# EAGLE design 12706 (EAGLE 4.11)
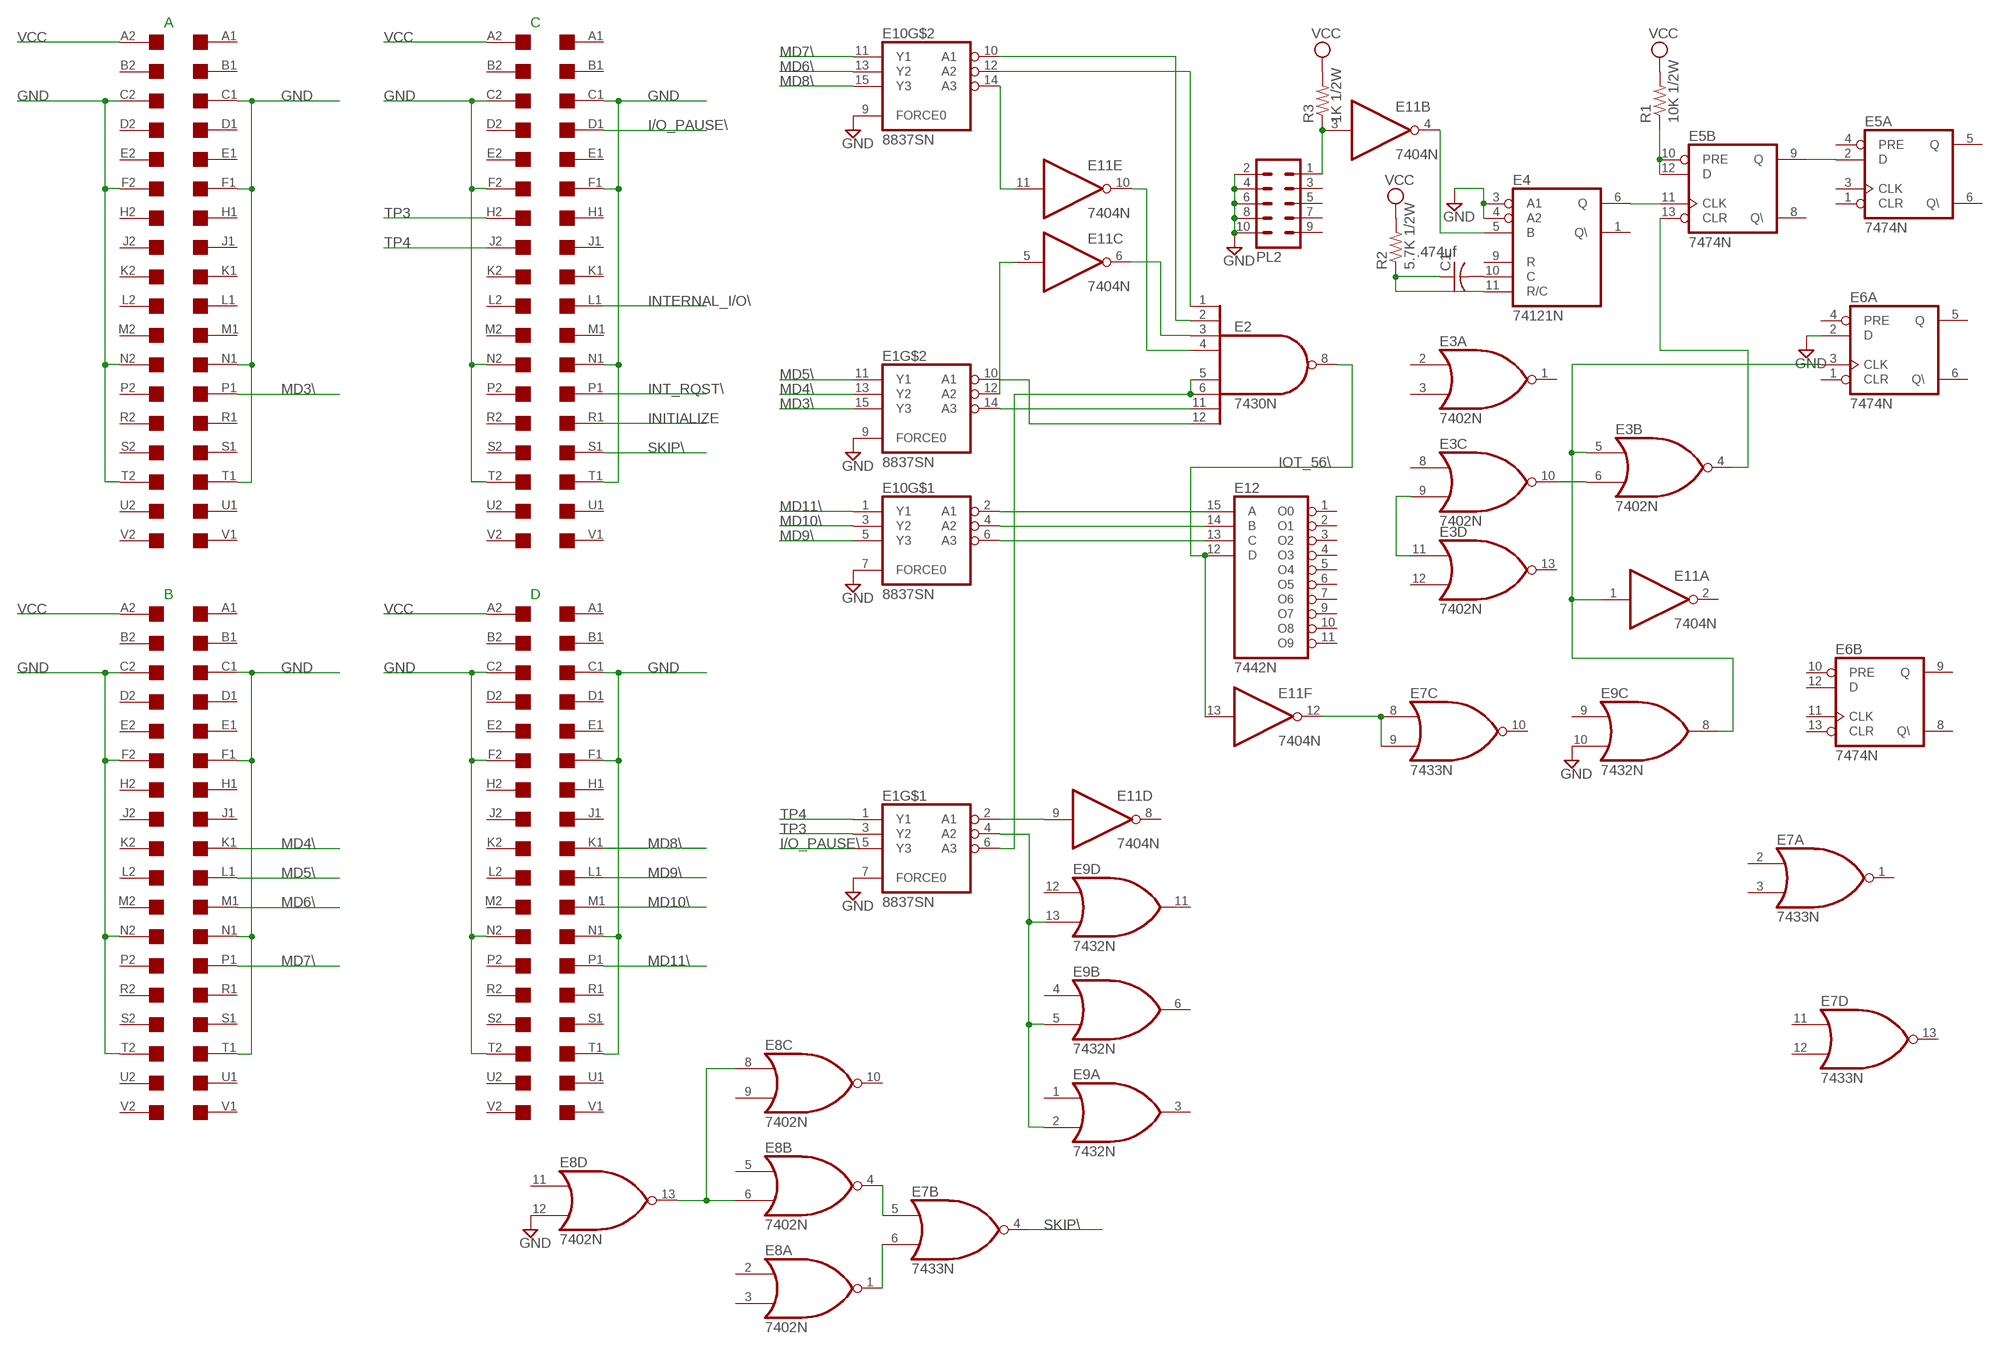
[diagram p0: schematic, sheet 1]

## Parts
A  DEC-FLIPCHIP  [DEC-FLIPCHIP]
B  DEC-FLIPCHIP  [DEC-FLIPCHIP]
C  DEC-FLIPCHIP  [DEC-FLIPCHIP]
C1  .474uf  C-US050-045X075  [C050-045X075]
D  DEC-FLIPCHIP  [DEC-FLIPCHIP]
E1  8837SN  [DIL16]
E2  7430N  [DIL14]
E3  7402N  [DIL14]
E4  74121N  [DIL14]
E5  7474N  74S74N  [DIL14]
E6  7474N  74S74N  [DIL14]
E7  7433N  74LS33N  [DIL14]
E8  7402N  [DIL14]
E9  7432N  [DIL14]
E10  8837SN  [DIL16]
E11  7404N  [DIL14]
E12  7442N  74LS42N  [DIL16]
PL2  10H  [10H]
R1  10K 1/2W  R-US_0204/7  [0204/7]
R2  5.7K 1/2W  R-US_0204/7  [0204/7]
R3  1K 1/2W  R-US_0204/7  [0204/7]

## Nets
GND [Power]: A.C1 A.C2 A.F1 A.F2 A.N1 A.N2 A.T1 A.T2 B.C1 B.C2 B.F1 B.F2 B.N1 B.N2 B.T1 B.T2 C.C1 C.C2 C.F1 C.F2 C.N1 C.N2 C.T1 C.T2 D.C1 D.C2 D.F1 D.F2 D.N1 D.N2 D.T1 D.T2 E1.7(FORCE0) E1.9(FORCE0) E4.3(A1) E4.4(A2) E6.2(A:D) E8.12(D:I1) E9.10(C:I1) E10.7(FORCE0) E10.9(FORCE0) PL2.2 PL2.4 PL2.6 PL2.8 PL2.10
I/O_PAUSE\: C.D1 E1.5(Y3)
INITIALIZE: C.R1
INT_RQST\: C.P1
INTERNAL_I/O\: C.L1
IOT_56\: E2.8(O) E11.13(F:I) E12.12(D)
MD3\: A.P1 E1.15(Y3)
MD4\: B.K1 E1.13(Y2)
MD5\: B.L1 E1.11(Y1)
MD6\: B.M1 E10.13(Y2)
MD7\: B.P1 E10.11(Y1)
MD8\: D.K1 E10.15(Y3)
MD9\: D.L1 E10.5(Y3)
MD10\: D.M1 E10.3(Y2)
MD11\: D.P1 E10.1(Y1)
N$1: E1.14(A3) E2.11(I6)
N$2: E1.10(A1) E2.12(I7)
N$3: E10.2(A1) E12.15(A)
N$4: E10.4(A2) E12.14(B)
N$5: E10.6(A3) E12.13(C)
N$6 [Power]: E7.6(B:I1) E8.1(A:O)
N$7: E7.8(C:I0) E7.9(C:I1) E11.12(F:O)
N$8: E1.2(A1) E11.9(D:I)
N$9 [Power]: E1.4(A2) E9.2(A:I1) E9.5(B:I1) E9.13(D:I1)
N$10: E1.6(A3) E2.5(I4) E2.6(I5)
N$11: E2.4(I3) E11.10(E:O)
N$12: E2.1(I0) E10.12(A2)
N$13: E2.2(I1) E10.10(A1)
N$14: E2.3(I2) E11.6(C:O)
N$15: E1.12(A2) E11.5(C:I)
N$16: E10.14(A3) E11.11(E:I)
N$17: E7.5(B:I0) E8.4(B:O)
N$18: E8.6(B:I1) E8.8(C:I0) E8.13(D:O)
N$19: C1.1 E4.11(R/C) R2.1
N$20: E5.2(A:D) E5.9(B:Q)
N$21: E5.10(B:PRE) E5.12(B:D) R1.1
N$22: E3.6(B:I1) E3.10(C:O)
N$23: E3.9(C:I1) E3.11(D:I0)
N$24: C1.2 E4.10(C)
N$25: E4.6(Q) E5.11(B:CLK)
N$26: E4.5(B) E11.4(B:O)
N$27: E11.3(B:I) PL2.1 R3.1
N$29: E3.4(B:O) E5.13(B:CLR)
N$30: E3.5(B:I0) E6.3(A:CLK) E9.8(C:O) E11.1(A:I)
SKIP\ [Power]: C.S1 E7.4(B:O)
TP3: C.H2 E1.3(Y2)
TP4: C.J2 E1.1(Y1)
VCC [Power]: A.A2 B.A2 C.A2 D.A2 R1.2 R2.2 R3.2
Unconnected: A.A1 A.B1 A.B2 A.D1 A.D2 A.E1 A.E2 A.H1 A.H2 A.J1 A.J2 A.K1 A.K2 A.L1 A.L2 A.M1 A.M2 A.P2 A.R1 A.R2 A.S1 A.S2 A.U1 A.U2 A.V1 A.V2 B.A1 B.B1 B.B2 B.D1 B.D2 B.E1 B.E2 B.H1 B.H2 B.J1 B.J2 B.K2 B.L2 B.M2 B.P2 B.R1 B.R2 B.S1 B.S2 B.U1 B.U2 B.V1 B.V2 C.A1 C.B1 C.B2 C.D2 C.E1 C.E2 C.H1 C.J1 C.K1 C.K2 C.L2 C.M1 C.M2 C.P2 C.R2 C.S2 C.U1 C.U2 C.V1 C.V2 D.A1 D.B1 D.B2 D.D1 D.D2 D.E1 D.E2 D.H1 D.H2 D.J1 D.J2 D.K2 D.L2 D.M2 D.P2 D.R1 D.R2 D.S1 D.S2 D.U1 D.U2 D.V1 D.V2 E3.1(A:O) E3.2(A:I0) E3.3(A:I1) E3.8(C:I0) E3.12(D:I1) E3.13(D:O) E4.1(Q\) E4.9(R) E5.1(A:CLR) E5.3(A:CLK) E5.4(A:PRE) E5.5(A:Q) E5.6(A:Q\) E5.8(B:Q\) E6.1(A:CLR) E6.4(A:PRE) E6.5(A:Q) E6.6(A:Q\) E6.8(B:Q\) E6.9(B:Q) E6.10(B:PRE) E6.11(B:CLK) E6.12(B:D) E6.13(B:CLR) E7.1(A:O) E7.2(A:I0) E7.3(A:I1) E7.10(C:O) E7.11(D:I0) E7.12(D:I1) E7.13(D:O) E8.2(A:I0) E8.3(A:I1) E8.5(B:I0) E8.9(C:I1) E8.10(C:O) E8.11(D:I0) E9.1(A:I0) E9.3(A:O) E9.4(B:I0) E9.6(B:O) E9.9(C:I0) E9.11(D:O) E9.12(D:I0) E11.2(A:O) E11.8(D:O) E12.1(O0) E12.2(O1) E12.3(O2) E12.4(O3) E12.5(O4) E12.6(O5) E12.7(O6) E12.9(O7) E12.10(O8) E12.11(O9) PL2.3 PL2.5 PL2.7 PL2.9

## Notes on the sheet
- A | C
- B | D

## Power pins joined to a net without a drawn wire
GND: E1.8(P:GND) E2.7(GND) E3.7(P:GND) E4.7(GND) E5.7(P:GND) E6.7(P:GND) E7.7(P:GND) E8.7(P:GND) E9.7(P:GND) E10.8(P:GND) E11.7(P:GND) E12.8(GND)
VCC: E1.16(P:VCC) E2.14(VCC) E3.14(P:VCC) E4.14(VCC) E5.14(P:VCC) E6.14(P:VCC) E7.14(P:VCC) E8.14(P:VCC) E9.14(P:VCC) E10.16(P:VCC) E11.14(P:VCC) E12.16(VCC)

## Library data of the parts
A B C D = con-dec:DEC-FLIPCHIP: Two-sided DEC Flip-Chip single card fingers
C1 = rcl:C-US: CAPACITOR, American symbol
E1 E10 = dec-con:8837: Hex inverting LINE RECEIVER
E2 = 74xx-us:74*30: 8-input NAND gate
E3 E8 = 74xx-us:74*02: Quad 2-input NOR gate
E4 = 74xx-us:74*121: Monostable MULTIVIBRATOR, schmitt trigger inputs
E5 E6 = 74xx-us:74*74: Dual D type positive edge triggered FLIP FLOP, preset and clear
E7 = 74xx-us:74*33: Quad 2-input NOR buffer, open collector
E9 = 74xx-us:74*32: Quad 2-input OR gate
E11 = 74xx-us:74*04: Hex INVERTER
E12 = 74xx-us:74*42: 4-line to 10-line DECODER (1-of-10)
PL2 = con-harting-h:10H: CONNECTOR
R1-R3 = rcl:R-US_: RESISTOR, American symbol

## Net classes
1 Power: width 0.381 mm, drill 0.381 mm, clearance 0.381 mm

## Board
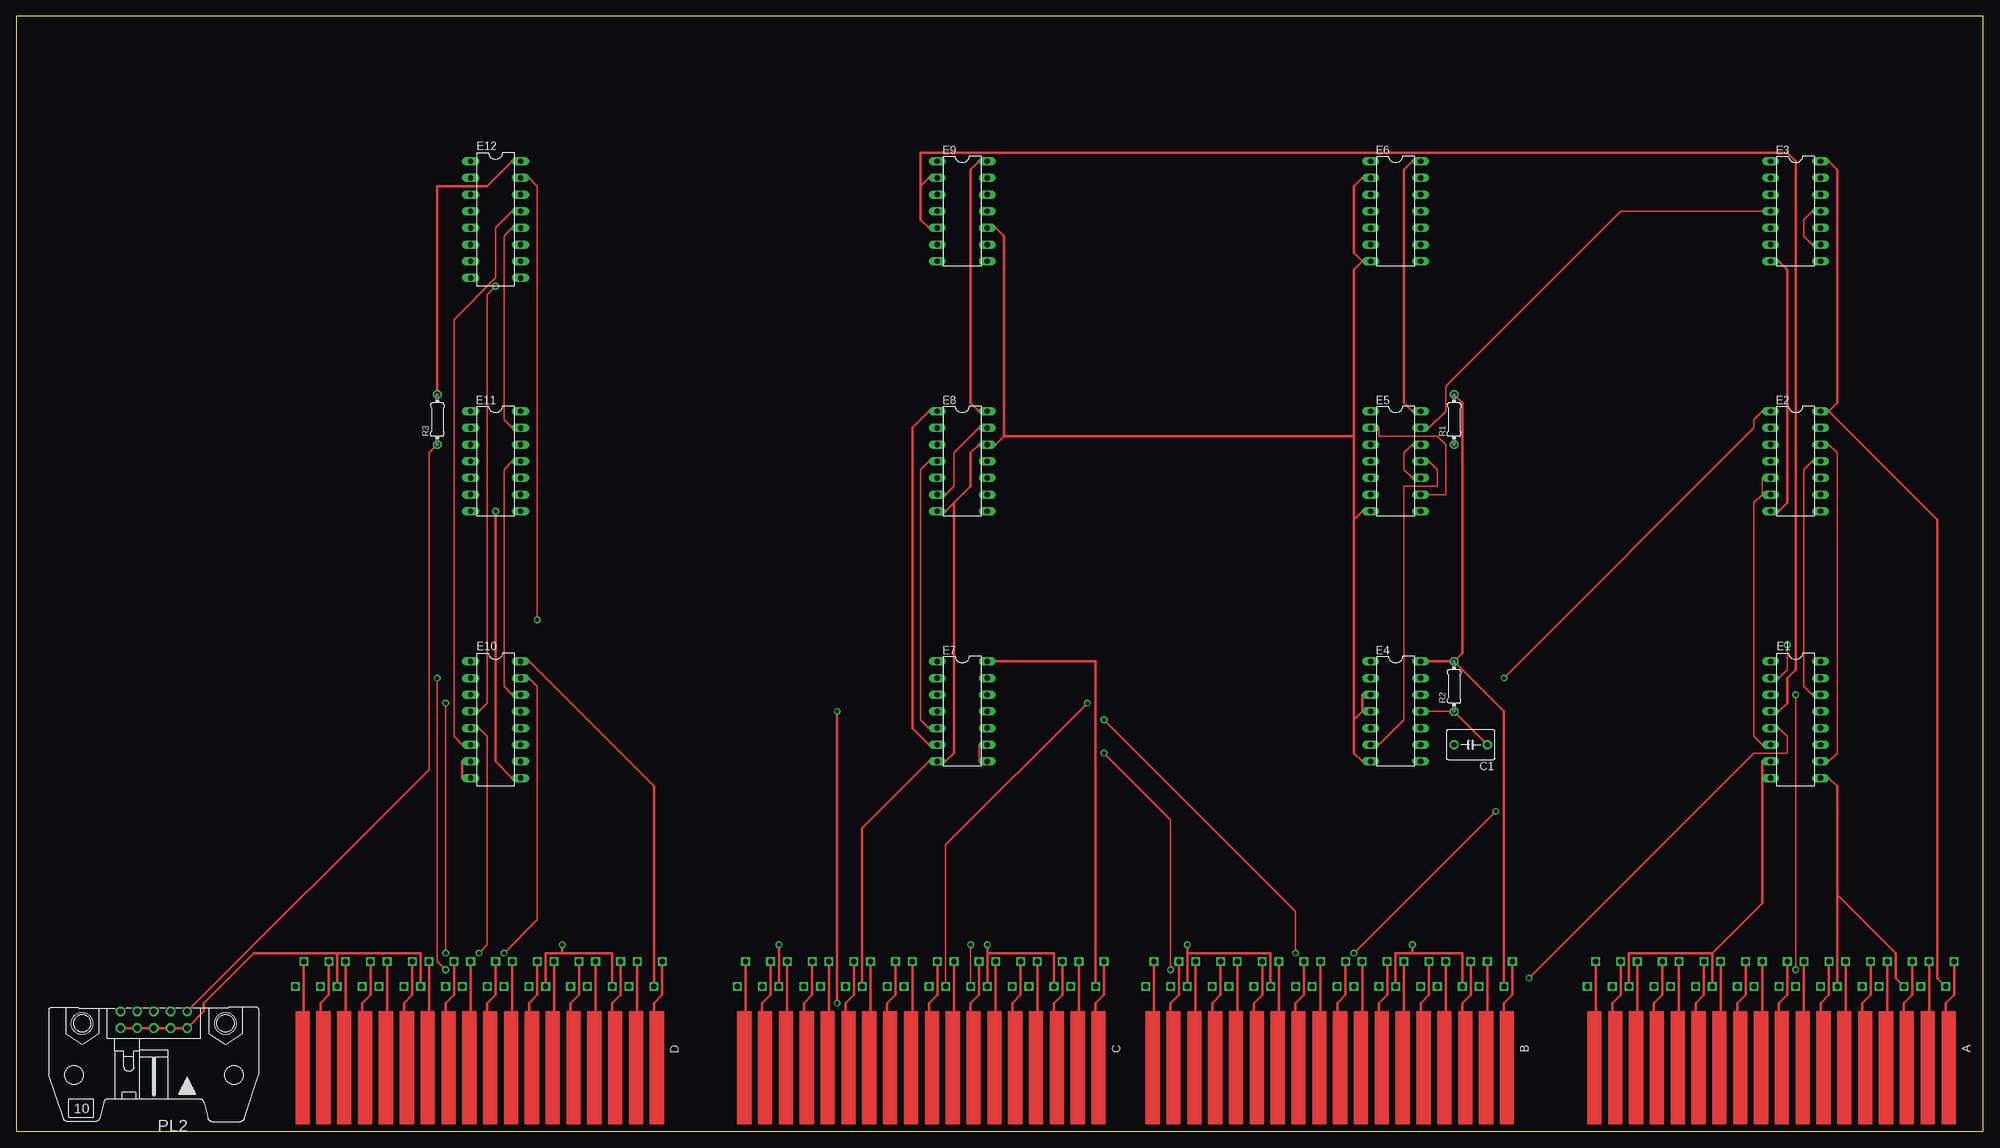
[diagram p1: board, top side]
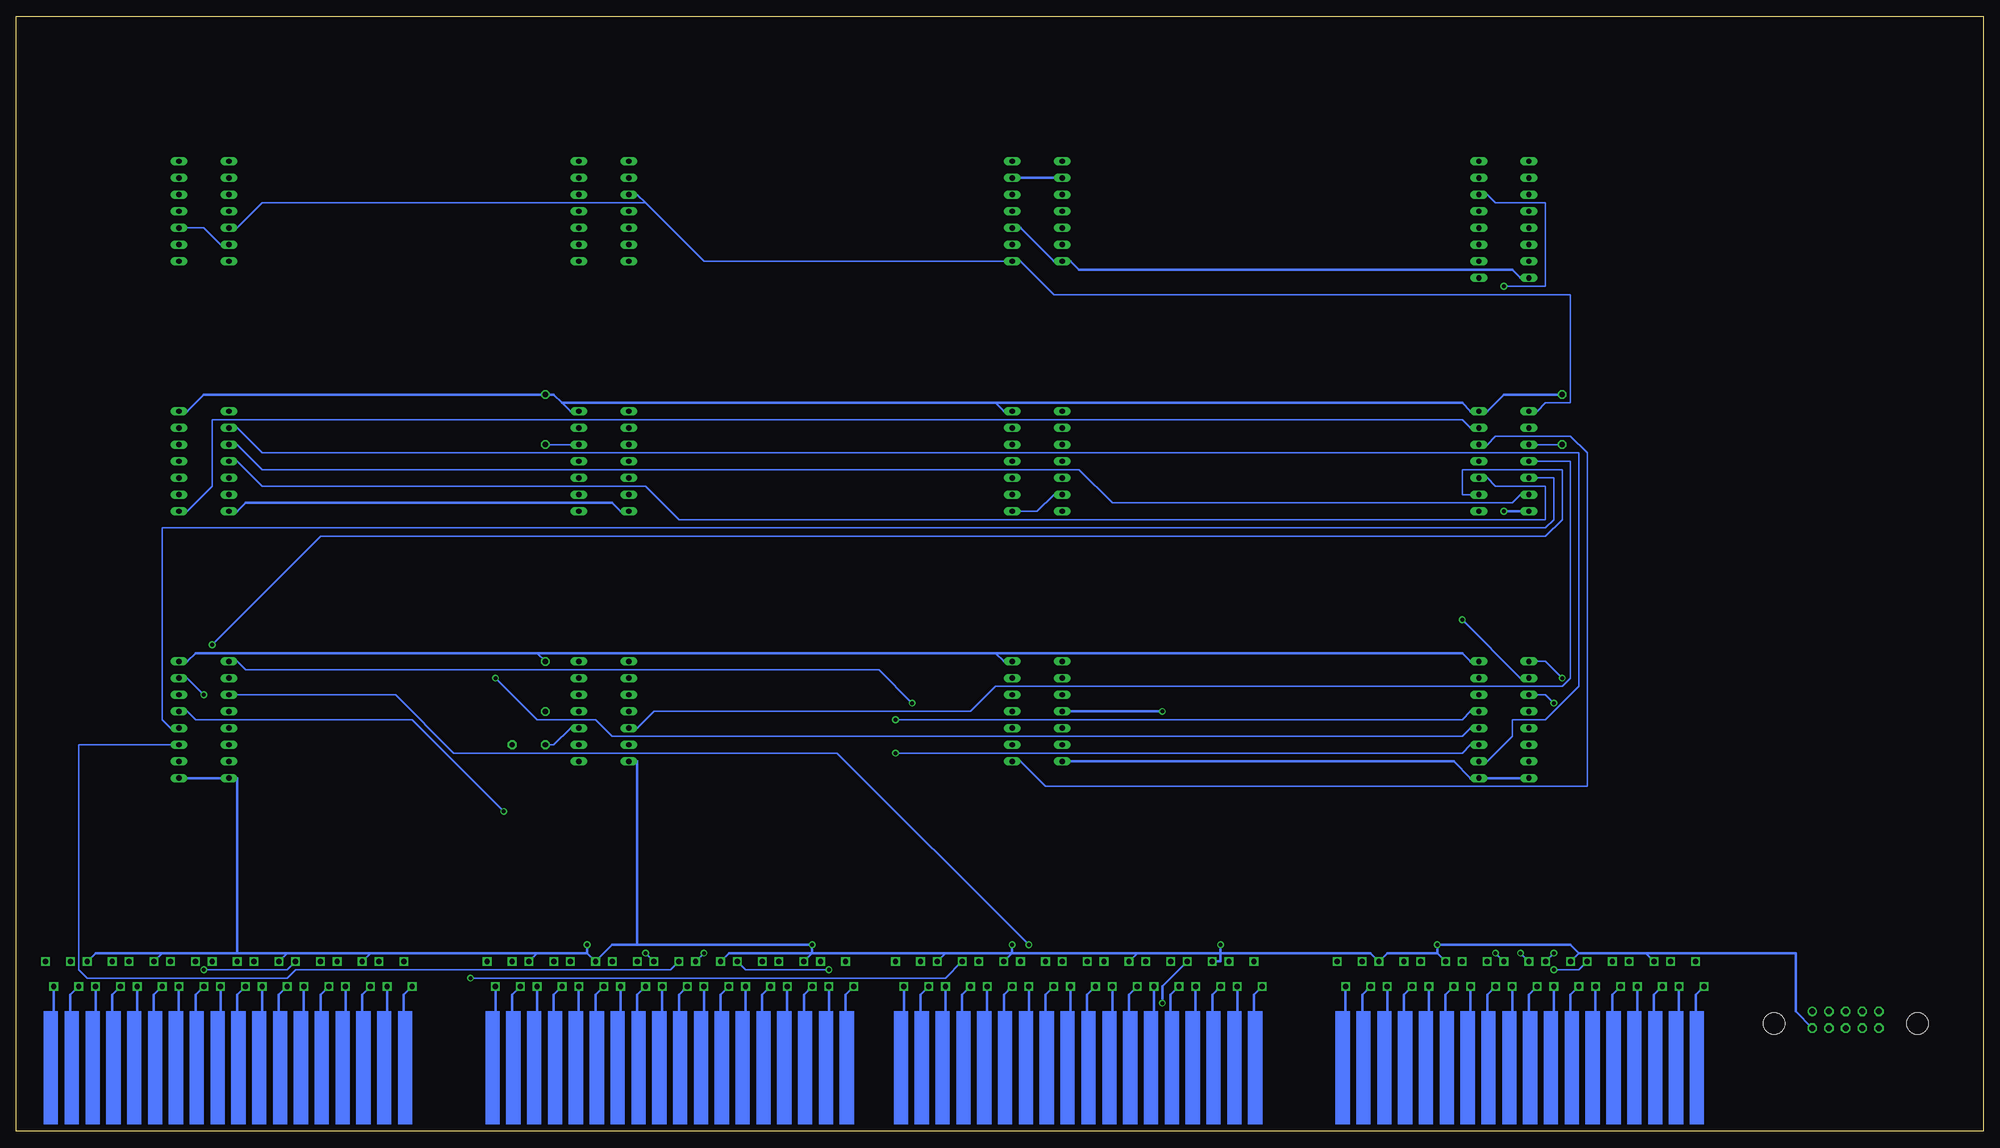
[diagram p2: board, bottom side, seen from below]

Size 299.7 x 169.85 mm. Coordinates in mm from the lower left corner, seen from the top.
Outline: 0,0 299.7,0 299.7,169.85 0,169.85 0,0
Copper layers (1*16): Top 0.035mm / dielectric 1.5mm / Bottom 0.035mm
Design rules "default": minimum track width 10mil, minimum drill 24mil, track to track 8mil, track to pad 8mil, pad to pad 8mil, via to via 8mil, smd to smd 8mil, copper to edge 40mil, drill to drill 8mil, minimum pad ring 10mil, minimum via ring 8mil, stop-mask expansion 4mil, vias tented up to drill 0mil, thermal gap 10mil

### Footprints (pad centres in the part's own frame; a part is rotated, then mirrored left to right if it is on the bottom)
DEC-FLIPCHIP = drill 0.813 square: A1 -7.62,27.94; A2 -3.81,26.67; B1 -7.62,24.13; B2 -3.81,22.86; C1 -7.62,21.59; C2 -3.81,20.32; D1 -7.62,17.78; D2 -3.81,16.51; E1 -7.62,15.24; E2 -3.81,13.97; F1 -7.62,11.43; F2 -3.81,10.16; H1 -7.62,8.89; H2 -3.81,7.62; J1 -7.62,5.08; J2 -3.81,3.81; K1 -7.62,2.54; K2 -3.81,1.27; L1 -7.62,-1.27; L2 -3.81,-2.54; M1 -7.62,-3.81; M2 -3.81,-5.08; N1 -7.62,-7.62; N2 -3.81,-8.89; P1 -7.62,-10.16; P2 -3.81,-11.43; R1 -7.62,-13.97; R2 -3.81,-15.24; S1 -7.62,-16.51; S2 -3.81,-17.78; T1 -7.62,-20.32; T2 -3.81,-21.59; U1 -7.62,-22.86; U2 -3.81,-24.13; V1 -7.62,-26.67; V2 -3.81,-27.94
C050-045X075 = drill 0.813 octagon: 1 -2.54,0; 2 2.54,0
DIL16 = drill 0.813 long: 1 -8.89,-3.81; 2 -6.35,-3.81; 3 -3.81,-3.81; 4 -1.27,-3.81; 5 1.27,-3.81; 6 3.81,-3.81; 7 6.35,-3.81; 8 8.89,-3.81; 9 8.89,3.81; 10 6.35,3.81; 11 3.81,3.81; 12 1.27,3.81; 13 -1.27,3.81; 14 -3.81,3.81; 15 -6.35,3.81; 16 -8.89,3.81
DIL14 = drill 0.813 long: 1 -7.62,-3.81; 2 -5.08,-3.81; 3 -2.54,-3.81; 4 0,-3.81; 5 2.54,-3.81; 6 5.08,-3.81; 7 7.62,-3.81; 8 7.62,3.81; 9 5.08,3.81; 10 2.54,3.81; 11 0,3.81; 12 -2.54,3.81; 13 -5.08,3.81; 14 -7.62,3.81
10H = drill 0.914 round: 1 -5.08,-1.27 | drill 0.914 octagon: 2 -5.08,1.27; 3 -2.54,-1.27; 4 -2.54,1.27; 5 0,-1.27; 6 0,1.27; 7 2.54,-1.27; 8 2.54,1.27; 9 5.08,-1.27; 10 5.08,1.27 | hole 3.302: -10.922,0.533; 10.922,0.533
0204/7 = drill 0.813 octagon: 1 -3.81,0; 2 3.81,0

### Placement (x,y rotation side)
A  267.33,18.25 270 top
B  200.02,18.25 270 top
C  137.79,18.25 270 top
C1  221.61,58.89 180 top
D  70.48,18.25 270 top
E1  271.14,62.7 270 top
E2  271.14,102.07 270 top
E3  271.14,140.17 270 top
E4  210.18,63.97 270 top
E5  210.18,102.07 270 top
E6  210.18,140.17 270 top
E7  144.14,63.97 270 top
E8  144.14,102.07 270 top
E9  144.14,140.17 270 top
E10  73.02,62.7 270 top
E11  73.02,102.07 270 top
E12  73.02,138.9 270 top
PL2  20.95,16.98 180 top
R1  219.07,108.42 90 top
R2  219.07,67.78 90 top
R3  64.13,108.42 90 top

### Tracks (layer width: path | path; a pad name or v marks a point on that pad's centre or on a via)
GND  (via drill 0.61)
  Top 0.381: E10.8 67.94,53.81 67.94,56.35 E10.7 | v73.02,94.45 73.02,56.35 75.56,53.81 E10.9 | C.N2 128.9,46.19 139.06,56.35 E7.7 141.6,56.35 142.87,57.62 142.87,95.72 | 142.87,95.72 145.41,98.26 145.41,103.34 146.68,104.61 E8.12 149.22,104.61 150.49,105.88 | 142.87,95.72 141.6,94.45 E8.7 | 150.49,105.88 150.49,136.36 149.22,137.63 E9.10 | E2.7 268.6,94.45 269.87,95.72 269.87,131.28 268.6,132.55 E3.7 | 205.1,132.55 203.83,133.82 203.83,143.98 205.1,145.25 E6.2 | 205.1,132.55 E6.7 205.1,132.55 | 203.83,62.7 203.83,57.62 205.1,56.35 E4.7 | 203.83,62.7 205.1,63.97 | 205.1,63.97 E4.4 205.1,63.97 | 205.1,63.97 205.1,66.51 E4.3 | 203.83,93.18 205.1,94.45 E5.7 | 203.83,93.18 203.83,62.7 | 205.1,132.55 203.83,131.28 203.83,105.88 | 203.83,105.88 203.83,93.18 | A.T2 245.74,27.14 258.44,27.14 | 258.44,27.14 A.N2 | 266.06,53.81 266.06,56.35 E1.7 | 266.06,53.81 E1.8 266.06,53.81 | 277.49,36.03 277.49,52.54 276.22,53.81 E1.9 | 277.49,36.03 A.F2 | A.C2 286.38,23.33 286.38,27.14 277.49,36.03 | 258.44,27.14 266.06,34.76 266.06,53.81 | B.F2 210.18,27.14 212.72,27.14 | 212.72,27.14 220.34,27.14 B.C2 | v212.72,28.41 212.72,27.14 | 48.89,27.14 D.T2 | 48.89,27.14 61.59,27.14 D.N2 | PL2.10 PL2.8 PL2.6 PL2.4 PL2.2 28.57,18.25 28.57,19.52 36.19,27.14 48.89,27.14 | 178.43,27.14 B.T2 | 178.43,27.14 191.13,27.14 B.N2 | 147.95,27.14 C.F2 | 147.95,27.14 158.11,27.14 C.C2 | D.F2 80.64,27.14 83.18,27.14 | 83.18,27.14 90.8,27.14 D.C2 | v116.2,28.41 C.T2 | v83.18,28.41 83.18,27.14 | v147.95,28.41 147.95,27.14 | v178.43,28.41 178.43,27.14 | 150.49,105.88 203.83,105.88
  Bottom 0.381: E10.8 70.48,53.81 75.56,53.81 E10.9 78.1,53.81 80.64,56.35 139.06,56.35 E7.7 | v73.02,94.45 70.48,94.45 E11.7 | E12.8 70.48,130.01 71.75,131.28 137.79,131.28 139.06,132.55 E9.7 141.6,132.55 146.68,137.63 E9.10 | E2.7 266.06,94.45 264.79,95.72 208.91,95.72 207.64,94.45 E5.7 | E1.9 273.68,53.81 268.6,53.81 E1.8 266.06,53.81 266.06,27.14 | 212.72,27.14 B.F1 208.91,28.41 205.1,28.41 | 212.72,27.14 220.34,27.14 | 220.34,27.14 B.C1 | 245.74,27.14 A.T1 | 220.34,27.14 245.74,27.14 | 258.44,27.14 A.N1 | 245.74,27.14 258.44,27.14 | 277.49,27.14 A.F1 | 258.44,27.14 266.06,27.14 | 266.06,27.14 277.49,27.14 | A.C1 287.65,27.14 277.49,27.14 | 212.72,27.14 v212.72,28.41 | 51.43,27.14 D.T1 | 61.59,27.14 51.43,27.14 | 61.59,27.14 D.N1 | PL2.2 28.57,18.25 28.57,27.14 51.43,27.14 | 83.18,27.14 D.F1 | 83.18,27.14 90.8,27.14 D.C1 93.34,27.14 116.2,27.14 | 116.2,27.14 116.2,25.87 C.T1 | 116.2,27.14 v116.2,28.41 | 128.9,27.14 C.N1 | 128.9,27.14 116.2,27.14 | 147.95,27.14 C.F1 | 147.95,27.14 128.9,27.14 | 158.11,27.14 C.C1 | 158.11,27.14 147.95,27.14 | 178.43,27.14 B.T1 | 178.43,27.14 158.11,27.14 | B.N1 191.13,27.14 178.43,27.14 | 83.18,27.14 v83.18,28.41 62.86,28.41 61.59,27.14 | 147.95,27.14 v147.95,28.41 | 178.43,27.14 v178.43,28.41 205.1,28.41 | 205.1,28.41 205.1,56.35 E4.7
I/O_PAUSE\  (via drill 0.61)
  Top 0.254: v230.5,23.33 264.79,57.62 269.87,57.62 269.87,60.16 268.6,61.43 E1.5
  Bottom 0.254: C.D1 158.11,23.33 v230.5,23.33
IOT_56\
  Top 0.254: E11.13 75.56,107.15 74.29,108.42 74.29,136.36 75.56,137.63 E12.12
  Bottom 0.254: E2.8 273.68,94.45 269.87,98.26 269.87,108.42 79.37,108.42 78.1,107.15 E11.13
MD3\  (via drill 0.61)
  Top 0.254: v271.14,24.6 v271.14,66.51
  Bottom 0.254: A.P1 258.44,24.6 v271.14,24.6 | v271.14,66.51 273.68,69.05 E1.15
MD4\  (via drill 0.61)
  Top 0.254: v225.42,48.73 v203.83,27.14
  Bottom 0.254: v203.83,27.14 B.K1 | v225.42,48.73 239.39,62.7 272.41,62.7 273.68,63.97 E1.13
MD5\
  Bottom 0.254: B.L1 200.02,24.6 257.17,24.6 258.44,23.33 288.92,23.33 290.19,24.6 290.19,58.89 276.22,58.89 E1.11
MD6\  (via drill 0.61)
  Top 0.254: v165.73,62.7 194.94,33.49 v194.94,27.14
  Bottom 0.254: v165.73,62.7 79.37,62.7 78.1,63.97 E10.13 | v194.94,27.14 B.M1
MD7\  (via drill 0.61)
  Top 0.254: v165.73,57.62 175.89,47.46 v175.89,24.6
  Bottom 0.254: v165.73,57.62 79.37,57.62 78.1,58.89 E10.11 | v175.89,24.6 188.59,24.6 B.P1
MD8\  (via drill 0.61)
  Top 0.254: v74.29,27.14 79.37,32.22 79.37,67.78 78.1,69.05 E10.15
  Bottom 0.254: D.K1 v74.29,27.14
MD9\  (via drill 0.61)
  Top 0.254: v70.48,27.14 71.75,28.41 71.75,60.16 70.48,61.43 E10.5
  Bottom 0.254: D.L1 v70.48,27.14
MD10\  (via drill 0.61)
  Top 0.254: v65.4,27.14 v65.4,65.24
  Bottom 0.254: v65.4,27.14 D.M1 | v65.4,65.24 66.67,66.51 67.94,66.51 E10.3
MD11\  (via drill 0.61)
  Top 0.254: v65.4,24.6 64.13,25.87 v64.13,69.05
  Bottom 0.254: D.P1 61.59,24.6 v65.4,24.6 | v64.13,69.05 66.67,71.59 67.94,71.59 E10.1
N$1
  Top 0.254: E1.14 273.68,66.51 272.41,67.78 272.41,100.8 273.68,102.07 E2.11
N$2
  Top 0.254: E1.10 276.22,56.35 277.49,57.62 277.49,103.34 276.22,104.61 E2.12
N$3  (via drill 0.61)
  Top 0.254: v79.37,77.94 79.37,143.98 78.1,145.25 E12.15
  Bottom 0.254: v79.37,77.94 70.48,69.05 E10.2
N$4  (via drill 0.61)
  Top 0.254: v73.02,128.74 71.75,127.47 71.75,65.24 70.48,63.97 E10.4
  Bottom 0.254: v73.02,128.74 66.67,128.74 66.67,141.44 74.29,141.44 75.56,142.71 E12.14
N$5
  Top 0.254: E10.6 67.94,58.89 66.67,60.16 66.67,123.66 73.02,130.01 73.02,137.63 75.56,140.17 E12.13
N$6
  Top 0.381: E7.6 139.06,58.89 136.52,61.43 136.52,107.15 139.06,109.69 E8.1
N$7
  Top 0.254: E7.8 146.68,56.35 146.68,58.89 E7.9
  Bottom 0.254: E11.12 75.56,104.61 74.29,105.88 62.86,105.88 60.32,103.34 60.32,52.54 142.87,52.54 146.68,56.35 E7.8
N$8  (via drill 0.61)
  Top 0.254: v269.87,74.13 269.87,70.32 268.6,69.05 E1.2
  Bottom 0.254: v269.87,74.13 253.36,90.64 66.67,90.64 64.13,93.18 64.13,100.8 79.37,100.8 79.37,96.99 78.1,96.99 E11.9
N$9
  Top 0.381: 137.79,143.98 137.79,138.9 139.06,137.63 E9.5 | 137.79,143.98 139.06,145.25 E9.2 | 137.79,143.98 137.79,149.06 269.87,149.06 271.14,147.79 271.14,70.32 269.87,69.05 269.87,65.24 268.6,63.97 E1.4
  Bottom 0.381: E9.13 146.68,145.25 141.6,145.25 E9.2
N$10
  Top 0.254: 266.06,96.99 264.79,95.72 264.79,60.16 266.06,58.89 E1.6 | 266.06,96.99 E2.6 266.06,96.99 | 266.06,96.99 266.06,99.53 E2.5
N$11
  Bottom 0.254: E11.10 75.56,99.53 74.29,98.26 66.67,98.26 66.67,93.18 198.75,93.18 203.83,98.26 262.25,98.26 266.06,102.07 E2.4
N$12  (via drill 0.61)
  Top 0.254: v226.69,69.05 264.79,107.15 264.79,108.42 266.06,109.69 E2.1
  Bottom 0.254: v226.69,69.05 220.34,62.7 211.45,62.7 208.91,60.16 79.37,60.16 78.1,61.43 E10.12
N$13
  Bottom 0.254: E10.10 75.56,56.35 71.75,60.16 71.75,62.7 66.67,62.7 61.59,67.78 61.59,103.34 262.25,103.34 266.06,107.15 E2.2
N$14
  Bottom 0.254: E11.6 70.48,96.99 71.75,95.72 132.71,95.72 137.79,100.8 262.25,100.8 266.06,104.61 E2.3
N$15
  Bottom 0.254: E1.12 276.22,61.43 277.49,62.7 277.49,91.91 66.67,91.91 65.4,93.18 65.4,99.53 67.94,99.53 E11.5
N$16
  Top 0.254: E10.14 75.56,66.51 74.29,67.78 74.29,100.8 75.56,102.07 E11.11
N$17
  Top 0.254: E7.5 139.06,61.43 137.79,62.7 137.79,100.8 139.06,102.07 E8.4
N$18
  Top 0.254: E8.13 146.68,107.15 142.87,103.34 142.87,98.26 141.6,96.99 E8.6
  Bottom 0.254: E8.6 141.6,96.99 144.14,94.45 146.68,94.45 E8.8
N$19
  Top 0.254: E4.11 215.26,63.97 R2.1 C1.1
N$20
  Top 0.254: E5.9 215.26,96.99 217.8,96.99 217.8,104.61 216.53,105.88 207.64,105.88 207.64,107.15 E5.2
N$21
  Top 0.254: E5.10 212.72,99.53 211.45,100.8 211.45,103.34 212.72,104.61 E5.12
  Bottom 0.254: R1.1 215.26,104.61 E5.12
N$22
  Bottom 0.254: E3.6 268.6,135.09 271.14,137.63 273.68,137.63 E3.10
N$23
  Top 0.254: E3.9 273.68,135.09 272.41,136.36 272.41,138.9 273.68,140.17 E3.11
N$24
  Bottom 0.254: C1.2 217.8,58.89 215.26,61.43 E4.10
N$25
  Top 0.254: E4.6 207.64,58.89 211.45,62.7 211.45,98.26 216.53,98.26 216.53,100.8 215.26,102.07 E5.11
N$26
  Bottom 0.254: E4.5 205.1,61.43 202.56,63.97 154.3,63.97 150.49,67.78 64.13,67.78 62.86,69.05 62.86,102.07 67.94,102.07 E11.4
N$27
  Top 0.254: PL2.1 62.86,55.08 62.86,103.34 R3.1
  Bottom 0.254: R3.1 67.94,104.61 E11.3
N$29
  Top 0.254: E5.13 215.26,107.15 217.8,109.69 217.8,113.5 244.47,140.17 266.06,140.17 E3.4
N$30
  Bottom 0.254: E11.1 67.94,109.69 66.67,110.96 62.86,110.96 62.86,127.47 141.6,127.47 146.68,132.55 E9.8 149.22,132.55 194.94,132.55 203.83,141.44 | 203.83,141.44 205.1,142.71 E6.3 | 203.83,141.44 262.25,141.44 266.06,137.63 E3.5
SKIP\  (via drill 0.61)
  Top 0.381: v125.09,19.52 v125.09,63.97
  Bottom 0.381: C.S1 125.09,22.06 v125.09,19.52 | v125.09,63.97 139.06,63.97 E7.4
TP3  (via drill 0.61)
  Top 0.254: v145.41,28.41 C.H2
  Bottom 0.254: v145.41,28.41 174.62,57.62 233.04,57.62 241.93,66.51 266.06,66.51 E1.3
TP4  (via drill 0.61)
  Top 0.254: C.J2 141.6,43.65 v163.19,65.24
  Bottom 0.254: v163.19,65.24 168.27,70.32 264.79,70.32 266.06,71.59 E1.1
VCC
  Top 0.381: D.A2 97.15,52.54 78.1,71.59 E10.16 | C.A2 164.46,71.59 149.22,71.59 E7.14 | R2.2 215.26,71.59 E4.14 | B.A2 226.69,63.97 R2.2 | 276.22,109.69 277.49,110.96 277.49,146.52 276.22,147.79 E3.14 | 276.22,109.69 E2.14 276.22,109.69 | A.A2 292.73,23.33 292.73,93.18 276.22,109.69 | R3.2 64.13,143.98 71.75,143.98 75.56,147.79 E12.16 | E8.14 146.68,109.69 145.41,110.96 145.41,146.52 146.68,147.79 E9.14 | E6.14 212.72,147.79 211.45,146.52 211.45,110.96 212.72,109.69 E5.14 | R2.2 220.34,72.86 220.34,110.96 R1.2
  Bottom 0.381: 220.34,72.86 272.41,72.86 273.68,71.59 E1.16 | R2.2 220.34,72.86 | 150.49,72.86 149.22,71.59 E7.14 | 220.34,72.86 150.49,72.86 | 150.49,72.86 79.37,72.86 78.1,71.59 E10.16 | R3.2 73.02,112.23 75.56,109.69 E11.14 78.1,109.69 79.37,110.96 150.49,110.96 | 216.53,110.96 217.8,112.23 R1.2 271.14,112.23 273.68,109.69 E2.14 | 216.53,110.96 215.26,109.69 E5.14 | 150.49,110.96 149.22,109.69 E8.14 | 150.49,110.96 216.53,110.96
